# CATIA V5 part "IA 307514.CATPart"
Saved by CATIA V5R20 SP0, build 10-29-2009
Part number: IA 307514
Revision: ANY
Definition: UNKNOWN
Nomenclature: IA 307514
Source: Unknown
Bounding box of the stored display mesh (mm): x -1.5 to 1.5, y -2.85 to 4.9, z -1.5 to 1.5
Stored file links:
  C:\Users\Utente\Desktop\IO LAVORO\3D X SITO CF\CUMSA\3D files FA\FA 053012-21\IA 307514.CATPart

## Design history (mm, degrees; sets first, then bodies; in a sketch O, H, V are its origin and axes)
Body1 "Cortar-Extruir3" (main body)
  Solid1: solid without history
